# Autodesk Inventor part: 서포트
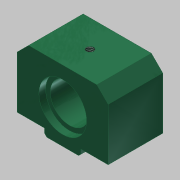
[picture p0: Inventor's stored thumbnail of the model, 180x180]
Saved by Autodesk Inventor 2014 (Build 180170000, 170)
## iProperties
Created: 2019-04
Part Number: 서포트
Material: 알루미늄 6061
Document SubType Name: Modeling
Designer: mduedu
Density: 1 g/cm^3
Appearance: Smooth - Dark Sea Green
Author: mduedu
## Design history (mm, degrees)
sketch "스케치1"
  geometry: L1 (3, 20)-(31, 20); L2 (31, 20)-(31, -20); L3 (31, -20)-(3, -20); L4 (0, -8)-(0, 8); L5 (0, 8)-(3, 8); L6 (3, 8)-(3, 20); L7 (0, 0)-(31, 0); L8 (0, -8)-(3, -8); L9 (3, -8)-(3, -20); 1 further point
  constraints: 18 end point, 3 symmetric about line, 2 horizontal, 2 midpoint, 2 parallel, 2 perpendicular, 1 coincident
  dimensions: "d3" = 31 distance between parallel lines of L4 L2; "d5" = 16 distance of L4.start L4.end; "d6" = 40 distance between parallel lines of L3 L1; "d7" = 3 distance between parallel lines of L4 L9
extrude "돌출1" new body sketch "스케치1" distance "d8" = 24; taper "d9" = 0 deg
chamfer "모따기1" distance "d10" = 5; stored, may be unused: second distance "d11" = 2, angle "d12" = 45 deg
chamfer "모따기2" distance "d13" = 1; stored, may be unused: second distance "d14" = 2, angle "d15" = 45 deg
sketch "스케치2"
  geometry: L1 (7, 0)-(-7, 0) reference; L2 (20, 3)-(8, 3) reference; 3 further points
  constraints: 1 midpoint, 1 vertical alignment
  dimensions: "d24" = 12 distance from line of point (0, 15) L2
hole "구멍1" sketch "스케치2" at (0, 15) diameter "d17" = 17; stored, may be unused: countersink angle "d21" = 90 deg, drill point angle "d23" = 118 deg; dims "d18" = 6, "d19" = 21, "d20" = 3, "d22" = 8
sketch "스케치3"
  geometry: L1 (0, 30)-(0, 0) reference; 3 further points
  constraints: 1 horizontal alignment, 1 midpoint
  dimensions: "d25" = 12 distance from line of point (12, 15) L1
hole "구멍2" sketch "스케치3" at (12, 15) diameter "d26" = 3.242; stored, may be unused: countersink angle "d30" = 90 deg, drill point angle "d32" = 118 deg; dims "d27" = 6, "d28" = 21, "d29" = 3, "d31" = 8
sketch "스케치4"
  geometry: L1 (0, -8)-(24, -8); L2 (24, 0.5)-(24, -16.5) reference; L3 (0, -28)-(0, -23) reference; 4 further points
  constraints: 2 end point, 2 symmetric about line, 1 horizontal, 1 horizontal alignment, 1 midpoint
  dimensions: "d33" = 6 distance from line of point (6, -22) L3; "d34" = 12 distance of point (18, -22) point (6, -22); "d35" = 28 distance of point (6, 6) point (6, -22); "d36" = 14 distance from line of point (6, -22) L1 (derived)
hole "구멍3" sketch "스케치4" at (6, -22), (18, -22), (18, 6), (6, 6) diameter "d37" = 3.242; stored, may be unused: countersink angle "d41" = 90 deg, drill point angle "d43" = 118 deg; dims "d38" = 9, "d39" = 21, "d40" = 3, "d42" = 11
node "솔리드1"
